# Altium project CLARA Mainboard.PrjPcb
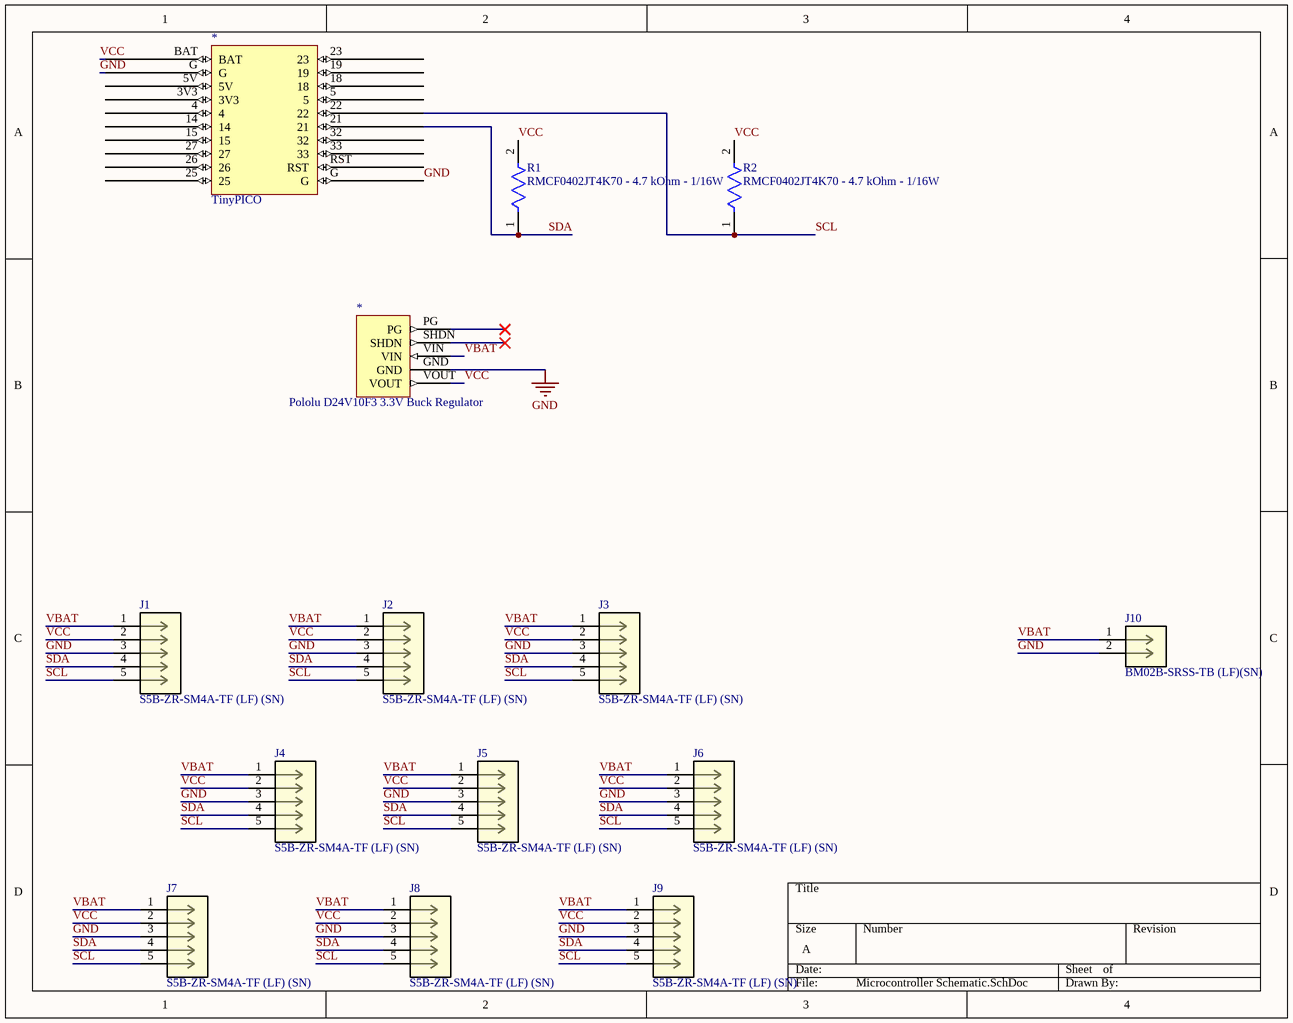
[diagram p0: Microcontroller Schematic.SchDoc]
1 sheet, 14 parts. Net scope: global (net labels, ports and power ports of the same name join across sheets).
Board file: CLARA_Mainboard.PcbDoc

## Sheet Microcontroller Schematic.SchDoc
size A; SheetNumber: 1; SheetTotal: 1

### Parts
(Parts that share a designator on the sheet are numbered #1, #2 ... from top to bottom, then left to right.)
*#1  TinyPICO  [TinyPICO Board]
*#2  Pololu D24V10F3 3.3V Buck Regulator  [PCBComponent_1]
J1  S5B-ZR-SM4A-TF (LF) (SN)  [CONN_S5B-ZR-SM4A-TF_JST]
J2  S5B-ZR-SM4A-TF (LF) (SN)  [CONN_S5B-ZR-SM4A-TF_JST]
J3  S5B-ZR-SM4A-TF (LF) (SN)  [CONN_S5B-ZR-SM4A-TF_JST]
J4  S5B-ZR-SM4A-TF (LF) (SN)  [CONN_S5B-ZR-SM4A-TF_JST]
J5  S5B-ZR-SM4A-TF (LF) (SN)  [CONN_S5B-ZR-SM4A-TF_JST]
J6  S5B-ZR-SM4A-TF (LF) (SN)  [CONN_S5B-ZR-SM4A-TF_JST]
J7  S5B-ZR-SM4A-TF (LF) (SN)  [CONN_S5B-ZR-SM4A-TF_JST]
J8  S5B-ZR-SM4A-TF (LF) (SN)  [CONN_S5B-ZR-SM4A-TF_JST]
J9  S5B-ZR-SM4A-TF (LF) (SN)  [CONN_S5B-ZR-SM4A-TF_JST]
J10  BM02B-SRSS-TB (LF)(SN)  [CONN_BM02B-SRSS-TB_JST]
R1  RMCF0402JT4K70 - 4.7 kOhm - 1/16W  [FP-RMCF0402-MFG]
R2  RMCF0402JT4K70 - 4.7 kOhm - 1/16W  [FP-RMCF0402-MFG]

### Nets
GND: *#1.G *#2.GND J1.3 J2.3 J3.3 J4.3 J5.3 J6.3 J7.3 J8.3 J9.3 J10.2
SCL: *#1.22 J1.5 J2.5 J3.5 J4.5 J5.5 J6.5 J7.5 J8.5 J9.5 R2.1
SDA: *#1.21 J1.4 J2.4 J3.4 J4.4 J5.4 J6.4 J7.4 J8.4 J9.4 R1.1
VBAT: *#2.VIN J1.1 J2.1 J3.1 J4.1 J5.1 J6.1 J7.1 J8.1 J9.1 J10.1
VCC: *#1.BAT *#2.VOUT J1.2 J2.2 J3.2 J4.2 J5.2 J6.2 J7.2 J8.2 J9.2 R1.2 R2.2

Not connected (* = marked no-connect by the designer): *#1 3V3 4 5 5V 14 15 18 19 23 25 26 27 32 33 RST; *#2 PG* SHDN*

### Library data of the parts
*#2 = Component_1
J1-J9 = S5B-ZR-SM4A-TF (LF) (SN): No Description Available; Mfr_Name: JST
J10 = BM02B-SRSS-TB (LF)(SN): No Description Available; Mfr_Name: JST
R1 R2 = CMP-2000-06988-2: 4.7kΩ ±5% 0.063W 0402 Thick Film Chip Resistor AEC-Q200 compliant; Resistance: 4.7kR; Power Rating: 63mW; Temperature Coefficient: 100ppm/°C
